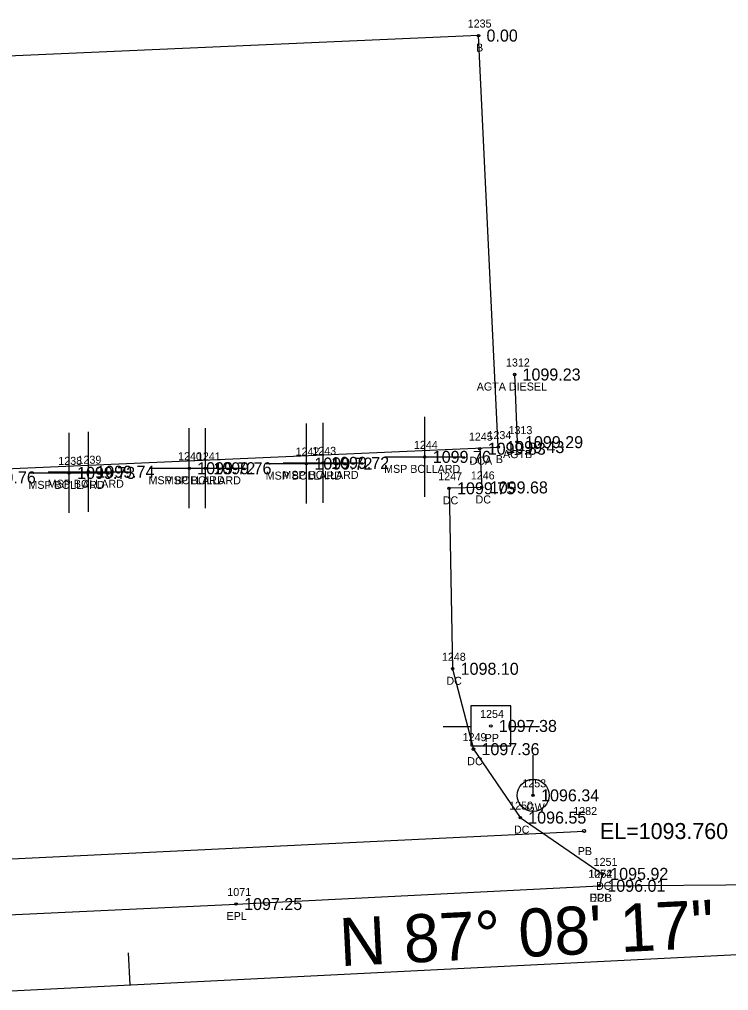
# Model space of a CAD drawing. Extents: x 1539151 to 1541799, y 1198646 to 1201165.
# Drawn here: x 1539579.5 to 1539668, y 1199359.7 to 1199481 of the extents above; entities that cross this region are included whole.
import ezdxf

# ---------------------------------------------------------------- set-up
doc = ezdxf.new("R2010")
doc.units = 0
for name, color, linetype in [('RD_EX_Bldg', 7, 'Continuous'), ('RD_EX_Bldg_txCode', 7, 'Continuous'), ('RD_EX_BldgApp', 7, 'Continuous'), ('RD_EX_BldgApp_txCode', 7, 'Continuous'), ('RD_EX_Conc', 7, 'Continuous'), ('RD_EX_Conc_txCode', 7, 'Continuous'), ('RD_EX_DR_Pipe', 7, 'Continuous'), ('RD_EX_DR_Pipe_txCode', 7, 'Continuous'), ('RD_EX_Misc', 7, 'Continuous'), ('RD_EX_Misc_txCode', 7, 'Continuous'), ('RD_EX_Road', 7, 'Continuous'), ('RD_EX_Road_txCode', 7, 'Continuous'), ('RD_EX_TX_Bldg_ELEV', 7, 'Continuous'), ('RD_EX_TX_BldgApp_ELEV', 7, 'Continuous'), ('RD_EX_TX_Conc_ELEV', 7, 'Continuous'), ('RD_EX_TX_Misc_ELEV', 7, 'Continuous'), ('RD_EX_TX_Road_ELEV', 7, 'Continuous'), ('RD_EX_TX_UT_ELEV', 7, 'Continuous'), ('RD_EX_UT', 7, 'Continuous'), ('RD_EX_UT_txCode', 7, 'Continuous'), ('RD_HC_Cl', 7, 'Continuous'), ('RD_HC_Data', 7, 'Continuous'), ('RD_HC_Data_Tic', 7, 'Continuous'), ('RD_HC_Survey_ELEV', 7, 'Continuous'), ('RD_SMD_Locator', 7, 'Continuous'), ('RD_TX_Pipe_ElevEX', 7, 'Continuous')]:
    doc.layers.add(name, color=color, linetype=linetype)

msp = doc.modelspace()

# ---------------------------------------------------------------- linework, layer by layer
at = {"layer": 'RD_EX_Bldg'}
msp.add_lwpolyline([(1539516.41, 1199473.69), (1539518.88, 1199422.27), (1539639.27, 1199427.57), (1539636.8, 1199478.99), (1539516.41, 1199473.69)], dxfattribs=at)
at = {"layer": 'RD_EX_BldgApp'}
msp.add_line((1539641.3, 1199436.64), (1539641.61, 1199428.19), dxfattribs=at)
at = {"layer": 'RD_EX_Conc'}
msp.add_lwpolyline([(1539636.95, 1199427.37), (1539637.21, 1199422.53), (1539633.12, 1199422.42), (1539633.57, 1199399.87), (1539636.17, 1199389.83), (1539642.01, 1199381.28), (1539652.25, 1199374.25), (1539651.89, 1199372.76)], dxfattribs=at)
at = {"layer": 'RD_EX_DR_Pipe'}
msp.add_lwpolyline([(1539516.15, 1199399.37), (1539552.6, 1199374.87), (1539649.98, 1199379.6)], dxfattribs=at)
at = {"layer": 'RD_EX_Misc'}
for p, q in [((1539630.09, 1199421.35), (1539630.09, 1199431.35)), ((1539600.67, 1199419.93), (1539600.67, 1199429.93)), ((1539602.69, 1199419.92), (1539602.69, 1199429.92)), ((1539615.3, 1199420.51), (1539615.3, 1199430.51)), ((1539617.39, 1199420.6), (1539617.39, 1199430.6)), ((1539585.67, 1199419.35), (1539585.67, 1199429.35)), ((1539588.07, 1199419.49), (1539588.07, 1199429.49)), ((1539625.09, 1199426.35), (1539635.09, 1199426.35)), ((1539595.67, 1199424.93), (1539605.67, 1199424.93)), ((1539597.69, 1199424.92), (1539607.69, 1199424.92)), ((1539610.3, 1199425.51), (1539620.3, 1199425.51)), ((1539612.39, 1199425.6), (1539622.39, 1199425.6)), ((1539580.67, 1199424.35), (1539590.67, 1199424.35)), ((1539583.07, 1199424.49), (1539593.07, 1199424.49))]:
    msp.add_line(p, q, dxfattribs=at)
at = {"layer": 'RD_EX_Road'}
msp.add_lwpolyline([(1539428.76, 1199454.93), (1539416.46, 1199395.23), (1539420.91, 1199377.84), (1539428.29, 1199368.53), (1539440.24, 1199363.06), (1539462.84, 1199364.11), (1539506.12, 1199366.59), (1539554.03, 1199368.02), (1539606.53, 1199370.48), (1539651.89, 1199372.76), (1539672.94, 1199372.91), (1539707.02, 1199374.85), (1539748.7, 1199377.62), (1539769.05, 1199378.19), (1539812.94, 1199380.16), (1539830.48, 1199381.23), (1539857.01, 1199382.87), (1539908.22, 1199385.45), (1539955.82, 1199389.74), (1539996.13, 1199397.4), (1540037.85, 1199410.51), (1540050.26, 1199415.61), (1540093.12, 1199444.78)], dxfattribs=at)
at = {"layer": 'RD_EX_UT'}
for p, q in [((1539640.84, 1199395.23), (1539635.84, 1199395.23)), ((1539635.84, 1199395.23), (1539635.84, 1199390.23)), ((1539640.84, 1199390.23), (1539640.84, 1199395.23)), ((1539632.4, 1199392.67), (1539635.87, 1199392.67)), ((1539640.76, 1199392.67), (1539644.4, 1199392.67)), ((1539635.84, 1199390.23), (1539640.84, 1199390.23)), ((1539643.62, 1199384.06), (1539643.62, 1199389.06))]:
    msp.add_line(p, q, dxfattribs=at)
msp.add_circle((1539643.62, 1199384.06), 2, dxfattribs=at)
at = {"layer": 'RD_HC_Cl'}
msp.add_line((1539393.53, 1199350.4), (1539900.86, 1199375.77), dxfattribs=at)
at = {"layer": 'RD_HC_Data_Tic'}
msp.add_line((1539593.28, 1199360.39), (1539593.08, 1199364.38), dxfattribs=at)
at = {"layer": 'RD_SMD_Locator'}
for centre, radius in [((1539636.8, 1199478.99), 0.15), ((1539641.3, 1199436.64), 0.15), ((1539636.95, 1199427.37), 0.15), ((1539639.27, 1199427.57), 0.15), ((1539641.61, 1199428.19), 0.15), ((1539630.09, 1199426.35), 0.15), ((1539600.67, 1199424.93), 0.15), ((1539602.69, 1199424.92), 0.15), ((1539615.3, 1199425.51), 0.15), ((1539617.39, 1199425.6), 0.15), ((1539585.67, 1199424.35), 0.15), ((1539588.07, 1199424.49), 0.15), ((1539633.12, 1199422.42), 0.15), ((1539637.21, 1199422.53), 0.15), ((1539633.57, 1199399.87), 0.15), ((1539638.34, 1199392.73), 0.15), ((1539636.17, 1199389.83), 0.15), ((1539643.62, 1199384.06), 0.15), ((1539642.01, 1199381.28), 0.15), ((1539649.98, 1199379.6), 0.2), ((1539652.25, 1199374.25), 0.15), ((1539651.89, 1199372.76), 0.15), ((1539651.89, 1199372.76), 0.15), ((1539606.53, 1199370.48), 0.15)]:
    msp.add_circle(centre, radius, dxfattribs=at)

# ---------------------------------------------------------------- texts
at = {"layer": 'RD_EX_Bldg_txCode'}
for s, p in [('1235', (1539635.45, 1199479.99)), ('B', (1539636.49, 1199476.99)), ('1234', (1539637.92, 1199428.57)), ('B', (1539638.96, 1199425.57))]:
    msp.add_text(s, height=1, dxfattribs=at).set_placement(p)
at = {"layer": 'RD_EX_BldgApp_txCode'}
for s, p in [('1312', (1539640.23, 1199437.64)), ('AGTA DIESEL', (1539636.58, 1199434.64)), ('1313', (1539640.55, 1199429.19)), ('AGTB', (1539639.86, 1199426.19))]:
    msp.add_text(s, height=1, dxfattribs=at).set_placement(p)
at = {"layer": 'RD_EX_Conc_txCode'}
for s, p in [('1245', (1539635.6, 1199428.37)), ('DCA', (1539635.68, 1199425.37)), ('1247', (1539631.77, 1199423.42)), ('1246', (1539635.84, 1199423.53)), ('DC', (1539632.34, 1199420.42)), ('DC', (1539636.43, 1199420.53)), ('1248', (1539632.23, 1199400.87)), ('DC', (1539632.79, 1199397.87)), ('1249', (1539634.82, 1199390.83)), ('DC', (1539635.39, 1199387.83)), ('1250', (1539640.63, 1199382.28)), ('DC', (1539641.23, 1199379.28)), ('1251', (1539651.18, 1199375.25)), ('1252', (1539650.54, 1199373.76)), ('DC', (1539651.47, 1199372.25)), ('DCB', (1539650.64, 1199370.76))]:
    msp.add_text(s, height=1, dxfattribs=at).set_placement(p)
at = {"layer": 'RD_EX_DR_Pipe_txCode'}
for s, p in [('1282', (1539648.63, 1199381.6)), ('PB', (1539649.2, 1199376.6))]:
    msp.add_text(s, height=1, dxfattribs=at).set_placement(p)
at = {"layer": 'RD_EX_Misc_txCode'}
for s, p in [('1242', (1539613.96, 1199426.51)), ('1243', (1539616.04, 1199426.6)), ('1244', (1539628.74, 1199427.35)), ('1238', (1539584.32, 1199425.35)), ('1239', (1539586.72, 1199425.49)), ('1240', (1539599.28, 1199425.93)), ('1241', (1539601.63, 1199425.92)), ('MSP BOLLARD', (1539625.01, 1199424.35)), ('MSP BOLLARD', (1539595.59, 1199422.93)), ('MSP BOLLARD', (1539597.61, 1199422.92)), ('MSP BOLLARD', (1539610.22, 1199423.51)), ('MSP BOLLARD', (1539612.31, 1199423.6)), ('MSP BOLLARD', (1539580.59, 1199422.35)), ('MSP BOLLARD', (1539582.99, 1199422.49))]:
    msp.add_text(s, height=1, dxfattribs=at).set_placement(p)
at = {"layer": 'RD_EX_Road_txCode'}
for s, p in [('1074', (1539650.5, 1199373.76)), ('1071', (1539605.43, 1199371.48)), ('EPL', (1539650.69, 1199370.76)), ('EPL', (1539605.33, 1199368.48))]:
    msp.add_text(s, height=1, dxfattribs=at).set_placement(p)
at = {"layer": 'RD_EX_TX_Bldg_ELEV'}
for s, p in [('0.00', (1539637.8, 1199478.24)), ('1099.43', (1539640.27, 1199426.82))]:
    msp.add_text(s, height=1.5, dxfattribs=at).set_placement(p)
at = {"layer": 'RD_EX_TX_BldgApp_ELEV'}
for s, p in [('1099.23', (1539642.3, 1199435.89)), ('1099.29', (1539642.61, 1199427.44))]:
    msp.add_text(s, height=1.5, dxfattribs=at).set_placement(p)
at = {"layer": 'RD_EX_TX_Conc_ELEV'}
for s, p in [('1099.83', (1539637.95, 1199426.62)), ('1099.75', (1539634.12, 1199421.67)), ('1099.68', (1539638.21, 1199421.78)), ('1098.10', (1539634.57, 1199399.12)), ('1097.36', (1539637.17, 1199389.08)), ('1096.55', (1539643.01, 1199380.53)), ('1095.92', (1539653.25, 1199373.5)), ('1096.01', (1539652.89, 1199372.01))]:
    msp.add_text(s, height=1.5, dxfattribs=at).set_placement(p)
at = {"layer": 'RD_EX_TX_Misc_ELEV'}
for s, p in [('1099.72', (1539616.3, 1199424.76)), ('1099.72', (1539618.39, 1199424.85)), ('1099.76', (1539631.09, 1199425.6)), ('1099.73', (1539586.67, 1199423.6)), ('1099.74', (1539589.07, 1199423.74)), ('1099.72', (1539601.67, 1199424.18)), ('1099.76', (1539603.69, 1199424.17)), ('1099.76', (1539574.26, 1199423.03))]:
    msp.add_text(s, height=1.5, dxfattribs=at).set_placement(p)
at = {"layer": 'RD_EX_TX_Road_ELEV'}
for s, p in [('1096.01', (1539652.89, 1199372.01)), ('1097.25', (1539607.53, 1199369.73))]:
    msp.add_text(s, height=1.5, dxfattribs=at).set_placement(p)
at = {"layer": 'RD_EX_TX_UT_ELEV'}
msp.add_text('1096.34', height=1.5, dxfattribs=at).set_placement((1539644.62, 1199383.31))
at = {"layer": 'RD_EX_UT_txCode'}
for s, p in [('1254', (1539637, 1199393.73)), ('PP', (1539637.57, 1199390.73)), ('1253', (1539642.27, 1199385.06)), ('GW', (1539642.77, 1199382.06))]:
    msp.add_text(s, height=1, dxfattribs=at).set_placement(p)
at = {"layer": 'RD_HC_Data'}
msp.add_text('N 87%%d 08\' 17" E', height=6, rotation=2.8619, dxfattribs=at).set_placement((1539619.57, 1199362.71))
at = {"layer": 'RD_HC_Survey_ELEV'}
msp.add_text('1097.38', height=1.5, dxfattribs=at).set_placement((1539639.34, 1199391.98))
at = {"layer": 'RD_TX_Pipe_ElevEX'}
msp.add_text('EL=1093.760', height=2, dxfattribs=at).set_placement((1539651.98, 1199378.6))

doc.saveas('drawing.dxf')
